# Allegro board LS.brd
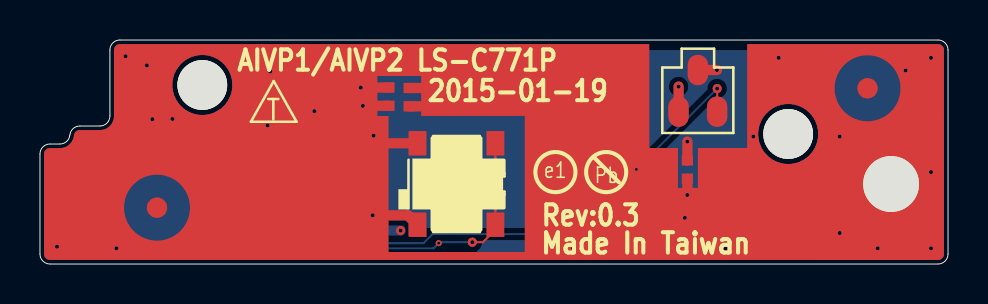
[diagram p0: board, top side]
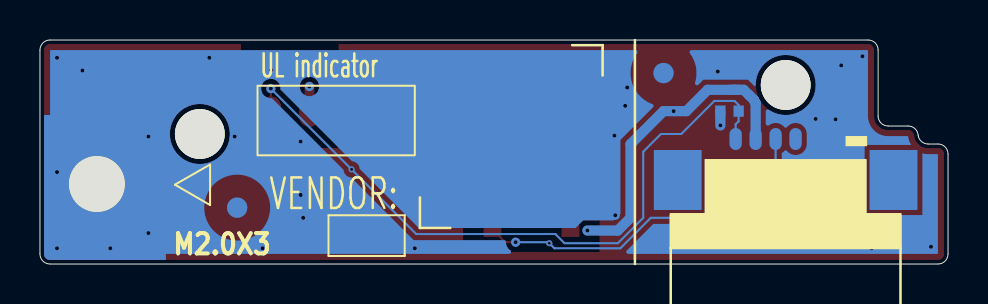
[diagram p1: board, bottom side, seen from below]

Outline 45.44 x 11.2 mm; copper layers: TOP, GND1, GND2, BOTTOM. Coordinates in mm from the lower left corner of the outline.
Outline path: 0,5.5 0,0.5 arc(0.15,0.15) 0.5,0 44.95,0 arc(45.3,0.15) 45.44,0.5 45.44,10.7 arc(45.3,11.05) 44.95,11.2 4,11.2 arc(3.65,11.05) 3.5,10.7 3.5,7.4 arc(3.35,7.05) 3,6.9 1.99,6.9 arc(1.66,6.77) 1.5,6.45 arc(1.34,6.13) 1,6 0.5,6 arc(0.15,5.85) 0,5.5

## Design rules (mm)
nets with their own width: min track width 0.508; nets +3VALW GND

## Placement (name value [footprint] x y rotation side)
C1  -  [C_0402]  10.68 8.71 90 bottom
C2  -  [C_0402]  11.39 7.64 180 bottom
C3  -  [C_0402]  17.46 7.91 90 top
C4  -  [C_0402]  18.48 8.8 270 top
C5  -  [C_0402]  32.4 4.26 90 top
FD1  -  [FIDUCIAL_C40M80]  41.42 8.79 0 top
FD2  -  [FIDUCIAL_C40M80]  5.86 2.82 0 top
FD3  -  [FIDUCIAL_C40M80]  35.57 2.82 180 bottom
FD4  -  [FIDUCIAL_C40M80]  14.24 9.55 180 bottom
H1  -  [H_2P5N]  37.44 6.5 0 top
H2  -  [H_2P8]  42.6 4 0 top
H3  -  [H_2P5N]  8.12 8.95 0 top
JPWRB  -  [ACES_88058-060N_6P]  5.63 6.25 180 bottom
NOREF  -  []  8.27 -34.9 0 top
NOREF#2  -  []  10.56 7.11 0 top
NOREF#3  -  []  3.95 18.57 0 top
NOREF#4  -  []  21.86 6.37 180 bottom
NOREF#5  -  []  42.69 8.91 180 bottom
NOREF#6  -  []  30.49 -0.48 180 bottom
SW1  -  [SW_SKRBAAE010_4P]  18.9 1.96 0 top
U1  -  [S-5711ACDL-M3T1S_SOT23-3]  32.93 9.7 180 top

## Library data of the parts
C1 = C_0402: tolerance: 0.1U_0402_16V4Z
C2 = C_0402: tolerance: 10P_0402_50V8J
C3-C5 = C_0402: tolerance: .1U_0402_16V7K
FD1-FD4 = FIDUCIAL_C40M80: tolerance: CF
H1 H3 = H_2P5N: tolerance: HOLEA
H2 = H_2P8: tolerance: HOLEA
JPWRB = ACES_88058-060N_6P: tolerance: ACES_88058-060N
SW1 = SW_SKRBAAE010_4P: tolerance: SKRBAAE010_4P
U1 = S-5711ACDL-M3T1S_SOT23-3: tolerance: AH1806-W-7 SC59 3P

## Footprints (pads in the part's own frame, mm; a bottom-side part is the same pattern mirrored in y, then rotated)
ACES_88058-060N_6P
  oval 0.61x1.092 smd: 1(0,0) 2(-1,0) 3(-2,0) 4(-3,0) 5(-4,0) 6(-5,0)
  rect 2.388x2.997 smd: 7(2.9,-2.05) 8(-7.9,-2.05)
C_0402
  rect 0.508x0.559 smd: 1(0,0) 2(0.914,0)
FIDUCIAL_C40M80
  round 1.016 smd: 1(0,0)
H_2P5N
  round 2.489 hole 2.489 unplated: (0,0)
H_2P8
  round 3.302 hole 2.794: 1(0,0)
S-5711ACDL-M3T1S_SOT23-3
  oval 1.016x1.524 smd: 1(0,0) 2(0.965,2.083) 3(-0.965,2.083)
SW_SKRBAAE010_4P
  rect 0.889x1.219 smd: 1(0,0) 2(3.9,0) 3(0,4.075) 4(3.9,4.075)

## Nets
+3VALW: C1.1 JPWRB.5 U1.2
GND: C1.2 C2.1 C3.1 C3.2 C4.1 C4.2 C5.1 C5.2 H2.1(TP-1) JPWRB.1 JPWRB.2 SW1.1 SW1.3 U1.1
LID_SW#: C2.2 JPWRB.6 U1.3
ON/OFF: JPWRB.4 SW1.2 SW1.4

Pads without a net: FD1 1; FD2 1; FD3 1; FD4 1; JPWRB 3 7 8

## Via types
v1: diameter 0.305, hole 0.152, TOP to BOTTOM, 2 vias
v2: diameter 0.457, hole 0.203, TOP to BOTTOM, 28 vias
v3: diameter 0.406, hole 0.203, TOP to BOTTOM, 4 vias

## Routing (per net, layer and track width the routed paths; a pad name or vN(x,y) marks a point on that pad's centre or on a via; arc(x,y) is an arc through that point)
+3VALW: length 16.9
  TOP w0.508: U1.2 v2(31.96,8.87)
  BOTTOM w0.508: v2(18.05,1.67) 16.52,1.67 15.89,2.31 15.89,5.99 14.24,7.64 v3(13.73,7.64) 13.1,7.64 12.03,8.71 C1.1 10.23,8.71 9.95,8.43 9.94,8.43 9.72,8.21 9.72,8.2 9.71,8.19 9.68,8.12 9.63,8.05 JPWRB.5
GND: length 45.9
  TOP w0.508: C3.1 v2(16.16,7.91) ; v2(16.65,2.44) 18.42,2.44 SW1.1 ; 19.57,7.9 19.56,7.88 C4.2 ; 19.7,8.79 19.69,8.8 C4.1 ; U1.1 v2(33.88,9.7) ; C5.1 v2(32.4,3.45) ; C5.2 v2(32.4,6.12) ; v2(16.7,6.42) 17.08,6.04 SW1.3 ; C3.2 v2(16.06,8.82)
  GND1 w0.203: H2.1 43.94,5.34 ; H2.1 42.6,5.83 ; H2.1 43.94,2.66 ; H2.1 42.6,2.17 ; H2.1 44.42,4 ; H2.1 40.77,4 ; H2.1 41.25,5.34 ; H2.1 41.25,2.66
  GND2 w0.203: 40.77,4 H2.1 ; H2.1 41.25,2.66 ; H2.1 43.94,2.66 ; H2.1 44.42,4 ; H2.1 43.94,5.34 ; H2.1 41.25,5.34 ; H2.1 42.6,5.83 ; H2.1 42.6,2.17
  BOTTOM w0.508: C1.2 v2(11.52,9.62) ; C2.1 v2(11.39,6.93) ; JPWRB.2 v2(6.63,7.25) ; JPWRB.1 v2(5.63,7.24)
  vias: v2(0.85,0.86) v2(3.82,0.79) v2(4.28,10.39) v2(26.68,0.79) v2(34.3,0.79) v2(35.7,6.37) v2(36.97,10.31) v2(40.02,6.37) v2(40.02,1.55) v2(41.92,0.79) v2(44.59,10.31) v2(44.59,4.6) v2(44.59,0.79) v3(5.35,9.93) v3(32.27,2.31) v3(43.32,9.68)
LID_SW#: length 34.5
  TOP w0.102: U1.3 v2(33.89,8.77)
  BOTTOM w0.102: JPWRB.6 10.63,6.99 10.48,7.14 C2.2 10.48,7.95 10.68,8.15 11.7,8.15 13.35,6.5 14.37,6.5 15.25,5.61 15.25,2.31 16.52,1.04 19.19,1.04 19.65,1.5 26.61,1.5 v1(29.85,4.73) v2(33.89,8.77)
ON/OFF: length 21.9
  TOP w0.102: v2(21.64,1.09) 22.16,1.09 22.79,1.72 SW1.2 SW1.4
  BOTTOM w0.102: v2(21.64,1.09) 20,1.09 v1(19.95,1.04) 19.7,0.79 16.4,0.79 14.87,2.31 11.19,2.31 8.63,4.87 JPWRB.4

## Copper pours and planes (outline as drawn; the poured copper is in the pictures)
+3VALW on GND2: 17.9,1.42 17.67,1.65 17.67,1.7 18.92,2.94 25.65,2.94 31.87,9.17 32.04,9.17 32.27,8.93 32.27,8.76 25.94,2.44 19.09,2.44 18.07,1.42
GND on TOP (solid shape): outline of 490 points within 0.2,0.2 45.24,11
GND on BOTTOM (solid shape): 12.83,10.69 12.92,10.64 12.91,10.53 12.61,9.83 12.66,9.07 12.61,8.95 12.49,8.97 12.24,9.22 11.22,9.22 10.15,9.22 10.02,9.22 9.74,8.94 9.73,8.94 9.68,8.88 9.62,8.93 9.62,8.96 6.8,9.65 8.96,7.71 9.07,7.71 9.12,7.62 9.12,7.03 9.06,6.93 8.96,6.94 8.57,7.05 8.21,6.86 8.13,6.82 8.05,6.86 7.43,7.02 7.07,6.49 7.07,6.01 7.43,5.48 8.05,5.64 8.13,5.68 8.21,5.64 8.26,5.59 8.32,5.54 8.32,4.45 10.77,2 14.75,2 16.07,0.68 16.09,0.57 16,0.51 0.51,0.51 0.51,5.49 1,5.49 1.14,5.5 1.28,5.53 1.28,2.45 4.18,2.45 4.18,5.95 1.85,5.95 1.94,6.14 2,6.35 2,6.39 3,6.39 3.71,6.69 4.01,7.4 4.01,10.69
GND on BOTTOM (solid shape): outline of 385 points within 14.74,0.2 45.24,10.69
GND on GND1: 0.51,0.51 0.51,5.49 1,5.49 1.67,5.75 2,6.39 3,6.39 3.71,6.69 4.01,7.4 4.01,10.69 44.94,10.69 44.94,0.51
GND on GND2: 0.51,0.51 0.51,5.49 1,5.49 1.67,5.75 2,6.39 3,6.39 3.71,6.69 4.01,7.4 4.01,10.69 44.94,10.69 44.94,0.51 ; 1 cut-out

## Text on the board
Ref Des/Silkscreen Bottom: M2.0X3
User.Comments: LSC771P | AIVP1/AIVP2 | 2015-01-19 | 2016-01-19 | Daisy | 0.3
PAGE_OUTLINE: 3.20 | 0.00 | 0.55 | 20.41 | 10.25
User.5: BOTTOM SIDE BOTTOM VIEW
User.11: PIN1 | 0.50 | 0.00 | 30.85
User.12: 4.45 | 3.20 | 0.00 | 24.33 | 10.25
User.16: PIN1 | 0.50 | 0.00 | 30.85
User.18: 4.45 | 3.20 | 0.00 | 18.60 | 4.52
User.19: 0.25 | 0.00 | 31.82
User.21: This height limit area is not any VIA hole
User.24: Bar code label area
User.42: GND4
User.43: GND5
User.45: trace Width | 1_0mm-4L(4mil 50 ohm)-stack-up-091123.pdf | LAYER | NAME | GND2 | BOT | TOP | GND1 | STACKUP: 4 LAYER | 50 ohm | 4 mil | THICKNESS=1.0mm | FIGURE | SIZE | 8.0 | 110.0 | 98.0 | DRILL CHART: TOP to BOTTOM | ALL UNITS ARE IN MILS | TOLERANCE | +3.0/-3.0 | +2.0/-2.0 | PLATED | NON-PLATED | QTY | 28 | 1 | 2
